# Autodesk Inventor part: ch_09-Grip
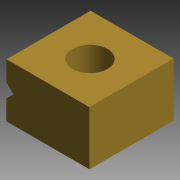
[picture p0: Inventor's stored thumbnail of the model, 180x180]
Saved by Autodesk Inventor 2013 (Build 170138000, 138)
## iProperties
Shininess: 0.0
Length Units: 11272
Angle Units: 11279
Time Units: 11290
Mass Units: 11283
Length Display Precision: 2
Angle Display Precision: 1
Compacted: True
Created: 1999-05
Part Number: ch_09-Grip
Document SubType Name: Modeling
Designer: Administrator
Density: 7.86 g/cm^3
Material: Steel, Mild
Mass: 29.2088 g
Surface Area: 18.6387 cm^2
Volume: 3.71614 cm^3
Density: 0.0
Volumn: 0.0
Area: 0.0
PropertySet Name: Model Information
Control State: 0
Master: False
Checked Out: False
Author: Administrator
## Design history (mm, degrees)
node "y-z Plane"
  node "x-z Plane"
  node "x-y Plane"
node "Extrusion1" dims "d2" = 19.05, "d3" = 0
  sketch "Sketch1"
    geometry: L1 (-9.398, -6.096)-(9.398, -6.096); L2 (9.398, -6.096)-(9.398, 6.096); L3 (9.398, 6.096)-(-9.398, 6.096); L4 (-9.398, 6.096)-(-9.398, -6.096); 1 further point
    constraints: 8 end point, 2 parallel, 1 horizontal, 1 perpendicular
    dimensions: "d0" = 18.796 distance of L1.start L1.end; "d1" = 12.192 distance of L1.end L2.end; "d17" = 9.398 distance from line of point (0, 0) L2 (= 0.5 x d0); "d18" = 6.096 distance from line of point (0, 0) L1 (= 0.5 x d1)
node "Extrusion2" dims "d7" = 19.05, "d8" = 0
  sketch "Sketch2"
    geometry: L1 (-9.398, 6.096)-(-9.398, -6.096) reference; L2 (-9.398, -1.588)-(-7.81, 0); L3 (-7.81, 0)-(-9.398, 1.588); 1 further point
    constraints: 4 end point, 2 point on line, 1 horizontal alignment, 1 perpendicular
    dimensions: "d4" = 1.5875 horizontal distance of L2.end L2.start; "d6" = 90 deg angle of L3 L2
node "Hole1" dims "d11" = 7.9248, "d12" = 9.525, "d13" = 6.35, "d14" = 60 deg, "d15" = 19.05, "d16" = 118 deg
  sketch "Sketch3"
    geometry: 2 further points
    constraints: 1 coincident
body "Solid1"
